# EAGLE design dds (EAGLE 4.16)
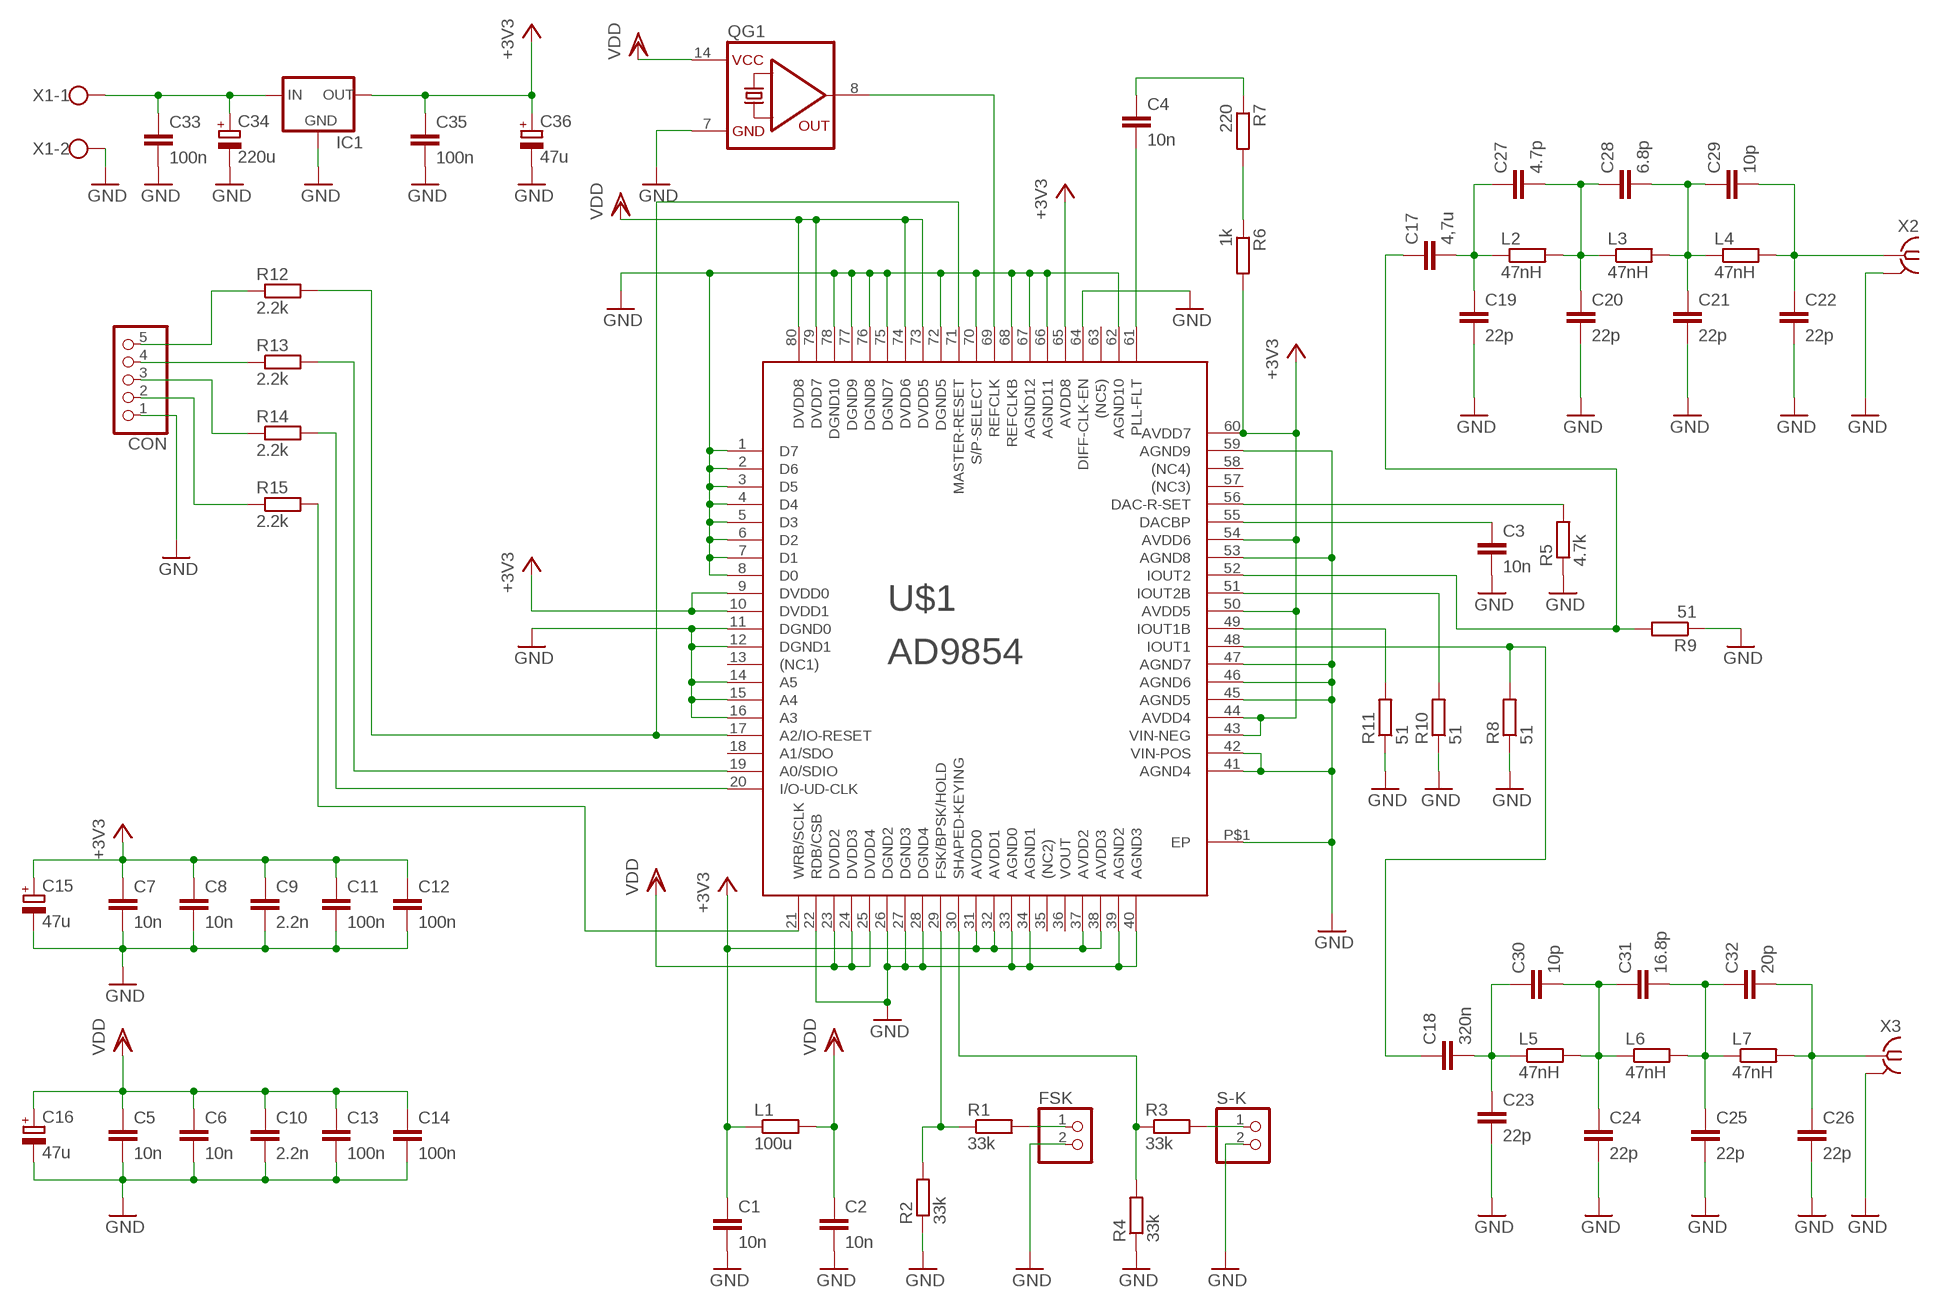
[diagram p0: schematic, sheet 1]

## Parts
C1  10n  C-EUC0805K  [C0805K]
C2  10n  C-EUC0805K  [C0805K]
C3  10n  C-EUC0805K  [C0805K]
C4  10n  C-EUC0805K  [C0805K]
C5  10n  C-EUC0805K  [C0805K]
C6  10n  C-EUC0805K  [C0805K]
C7  10n  C-EUC0805K  [C0805K]
C8  10n  C-EUC0805K  [C0805K]
C9  2.2n  C-EUC0603  [C0603]
C10  2.2n  C-EUC0603  [C0603]
C11  100n  C-EUC1206  [C1206]
C12  100n  C-EUC1206  [C1206]
C13  100n  C-EUC1206  [C1206]
C14  100n  C-EUC1206  [C1206]
C15  47u  CPOL-EUE2-4  [E2-4]
C16  47u  CPOL-EUE2-4  [E2-4]
C17  4,7u  C-EUC1206  [C1206]
C18  320n  C-EUC1206  [C1206]
C19  22p  C-EUC0805K  [C0805K]
C20  22p  C-EUC0805K  [C0805K]
C21  22p  C-EUC0805K  [C0805K]
C22  22p  C-EUC0805K  [C0805K]
C23  22p  C-EUC0805K  [C0805K]
C24  22p  C-EUC0805K  [C0805K]
C25  22p  C-EUC0805K  [C0805K]
C26  22p  C-EUC0805K  [C0805K]
C27  4.7p  C-EUC0805K  [C0805K]
C28  6.8p  C-EUC0805K  [C0805K]
C29  10p  C-EUC0805K  [C0805K]
C30  10p  C-EUC0805K  [C0805K]
C31  16.8p  C-EUC0805K  [C0805K]
C32  20p  C-EUC0805K  [C0805K]
C33  100n  C5/2.5  [C5B2.5]
C34  220u  CPOL-EUE2.5-6  [E2,5-6]
C35  100n  C5/2.5  [C5B2.5]
C36  47u  CPOL-EUE2-5  [E2-5]
CON  PINHD-1X5  [1X05]
FSK  PINHD-1X2  [1X02]
IC1  78XXS  [78XXS]
L1  100u  R-EU_0204/5  [0204/5]
L2  47nH  R-EU_M1206  [M1206]
L3  47nH  R-EU_M1206  [M1206]
L4  47nH  R-EU_M1206  [M1206]
L5  47nH  R-EU_M1206  [M1206]
L6  47nH  R-EU_M1206  [M1206]
L7  47nH  R-EU_M1206  [M1206]
QG1  QG5860  [DIL14S]
R1  33k  R-EU_M1206  [M1206]
R2  33k  R-EU_M1206  [M1206]
R3  33k  R-EU_M1206  [M1206]
R4  33k  R-EU_M1206  [M1206]
R5  4.7k  R-EU_R0805  [R0805]
R6  1k  R-EU_R0805  [R0805]
R7  220  R-EU_R0805  [R0805]
R8  51  R-EU_M1206  [M1206]
R9  51  R-EU_M1206  [M1206]
R10  51  R-EU_M1206  [M1206]
R11  51  R-EU_M1206  [M1206]
R12  2.2k  R-EU_0204/7  [0204/7]
R13  2.2k  R-EU_0204/7  [0204/7]
R14  2.2k  R-EU_0204/7  [0204/7]
R15  2.2k  R-EU_0204/7  [0204/7]
S-K  PINHD-1X2  [1X02]
U$1  AD9854  [TQFP80-917]
X1  W237-102  [W237-102]
X2  BU-SMA-H  [BU-SMA-H]
X3  BU-SMA-H  [BU-SMA-H]

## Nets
+3V3: C1.1 C7.1 C8.1 C9.1 C11.1 C12.1 C15.+ C35.1 C36.+ IC1.OUT L1.1 R6.2 U$1.9(DVDD0) U$1.10(DVDD1) U$1.31(AVDD0) U$1.32(AVDD1) U$1.37(AVDD2) U$1.38(AVDD3) U$1.43(VIN-NEG) U$1.44(AVDD4) U$1.50(AVDD5) U$1.54(AVDD6) U$1.60(AVDD7) U$1.65(AVDD8)
GND: C1.2 C2.2 C3.2 C5.2 C6.2 C7.2 C8.2 C9.2 C10.2 C11.2 C12.2 C13.2 C14.2 C15.- C16.- C19.2 C20.2 C21.2 C22.2 C23.2 C24.2 C25.2 C26.2 C33.2 C34.- C35.2 C36.- CON.1 FSK.2 IC1.GND QG1.7(GND) R2.1 R4.1 R5.1 R8.1 R9.1 R10.1 R11.1 S-K.2 U$1.1(D7) U$1.2(D6) U$1.3(D5) U$1.4(D4) U$1.5(D3) U$1.6(D2) U$1.7(D1) U$1.8(D0) U$1.11(DGND0) U$1.12(DGND1) U$1.14(A5) U$1.15(A4) U$1.16(A3) U$1.22(RDB/CSB) U$1.26(DGND2) U$1.27(DGND3) U$1.28(DGND4) U$1.33(AGND0) U$1.34(AGND1) U$1.39(AGND2) U$1.40(AGND3) U$1.41(AGND4) U$1.42(VIN-POS) U$1.45(AGND5) U$1.46(AGND6) U$1.47(AGND7) U$1.53(AGND8) U$1.59(AGND9) U$1.62(AGND10) U$1.64(DIFF-CLK-EN) U$1.66(AGND11) U$1.67(AGND12) U$1.68(REFCLKB) U$1.70(S/P-SELECT) U$1.72(DGND5) U$1.75(DGND7) U$1.76(DGND8) U$1.77(DGND9) U$1.78(DGND10) U$1.P$1(EP) X1.2 X2.2(GND) X3.2(GND)
N$1: R11.2 U$1.49(IOUT1B)
N$2: R1.1 R2.2 U$1.29(FSK/BPSK/HOLD)
N$3: FSK.1 R1.2
N$4: R3.1 R4.2 U$1.30(SHAPED-KEYING)
N$5: R3.2 S-K.1
N$6: C3.1 U$1.55(DACBP)
N$7: R5.2 U$1.56(DAC-R-SET)
N$8: C4.2 U$1.61(PLL-FLT)
N$9: C4.1 R7.1
N$10: R6.1 R7.2
N$11: QG1.8(OUT) U$1.69(REFCLK)
N$12: R10.2 U$1.51(IOUT2B)
N$13: C17.2 C19.1 C27.1 L2.1
N$14: C20.1 C27.2 C28.1 L2.2 L3.1
N$15: C21.1 C28.2 C29.1 L3.2 L4.1
N$16: C18.1 R8.2 U$1.48(IOUT1)
N$17: C17.1 R9.2 U$1.52(IOUT2)
N$18: C22.1 C29.2 L4.2 X2.1
N$19: C18.2 C23.1 C30.1 L5.1
N$20: C24.1 C30.2 C31.1 L5.2 L6.1
N$21: C25.1 C31.2 C32.1 L6.2 L7.1
N$22: C26.1 C32.2 L7.2 X3.1
N$23: R12.2 U$1.17(A2/IO-RESET) U$1.71(MASTER-RESET)
N$24: R13.2 U$1.19(A0/SDIO)
N$25: R14.2 U$1.20(I/O-UD-CLK)
N$26: R15.2 U$1.21(WRB/SCLK)
N$27: CON.5 R12.1
N$28: CON.4 R13.1
N$29: CON.3 R14.1
N$30: CON.2 R15.1
N$31: C33.1 C34.+ IC1.IN X1.1
VDD: C2.1 C5.1 C6.1 C10.1 C13.1 C14.1 C16.+ L1.2 QG1.14(VCC) U$1.23(DVDD2) U$1.24(DVDD3) U$1.25(DVDD4) U$1.73(DVDD5) U$1.74(DVDD6) U$1.79(DVDD7) U$1.80(DVDD8)
Unconnected: U$1.13((NC1)) U$1.18(A1/SDO) U$1.35((NC2)) U$1.36(VOUT) U$1.57((NC3)) U$1.58((NC4)) U$1.63((NC5))

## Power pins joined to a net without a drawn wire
GND: X2.3(GND) X2.4(GND) X2.5(GND) X3.3(GND) X3.4(GND) X3.5(GND)

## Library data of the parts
C1-C14 C17-C32 = rcl:C-EU: CAPACITOR, European symbol
C15 C16 C34 C36 = rcl:CPOL-EU: POLARIZED CAPACITOR, European symbol
C33 C35 = capacitor-wima:C: CAPACITOR
CON = pinhead:PINHD-1X5: PIN HEADER
FSK S-K = pinhead:PINHD-1X2: PIN HEADER
IC1 = v-reg:78XXS: VOLTAGE REGULATOR
L1-L7 R1-R15 = rcl:R-EU_: RESISTOR, European symbol
QG1 = crystal:QG5860: CRYSTAL RESONATOR
U$1 = analog-devices-dds:AD9854
X1 = con-wago-500:W237-102: WAGO SCREW CLAMP
X2 X3 = con-coax:BU-SMA-H: FEMALE SMA CONNECTOR Radiall distributor RS 193-9325

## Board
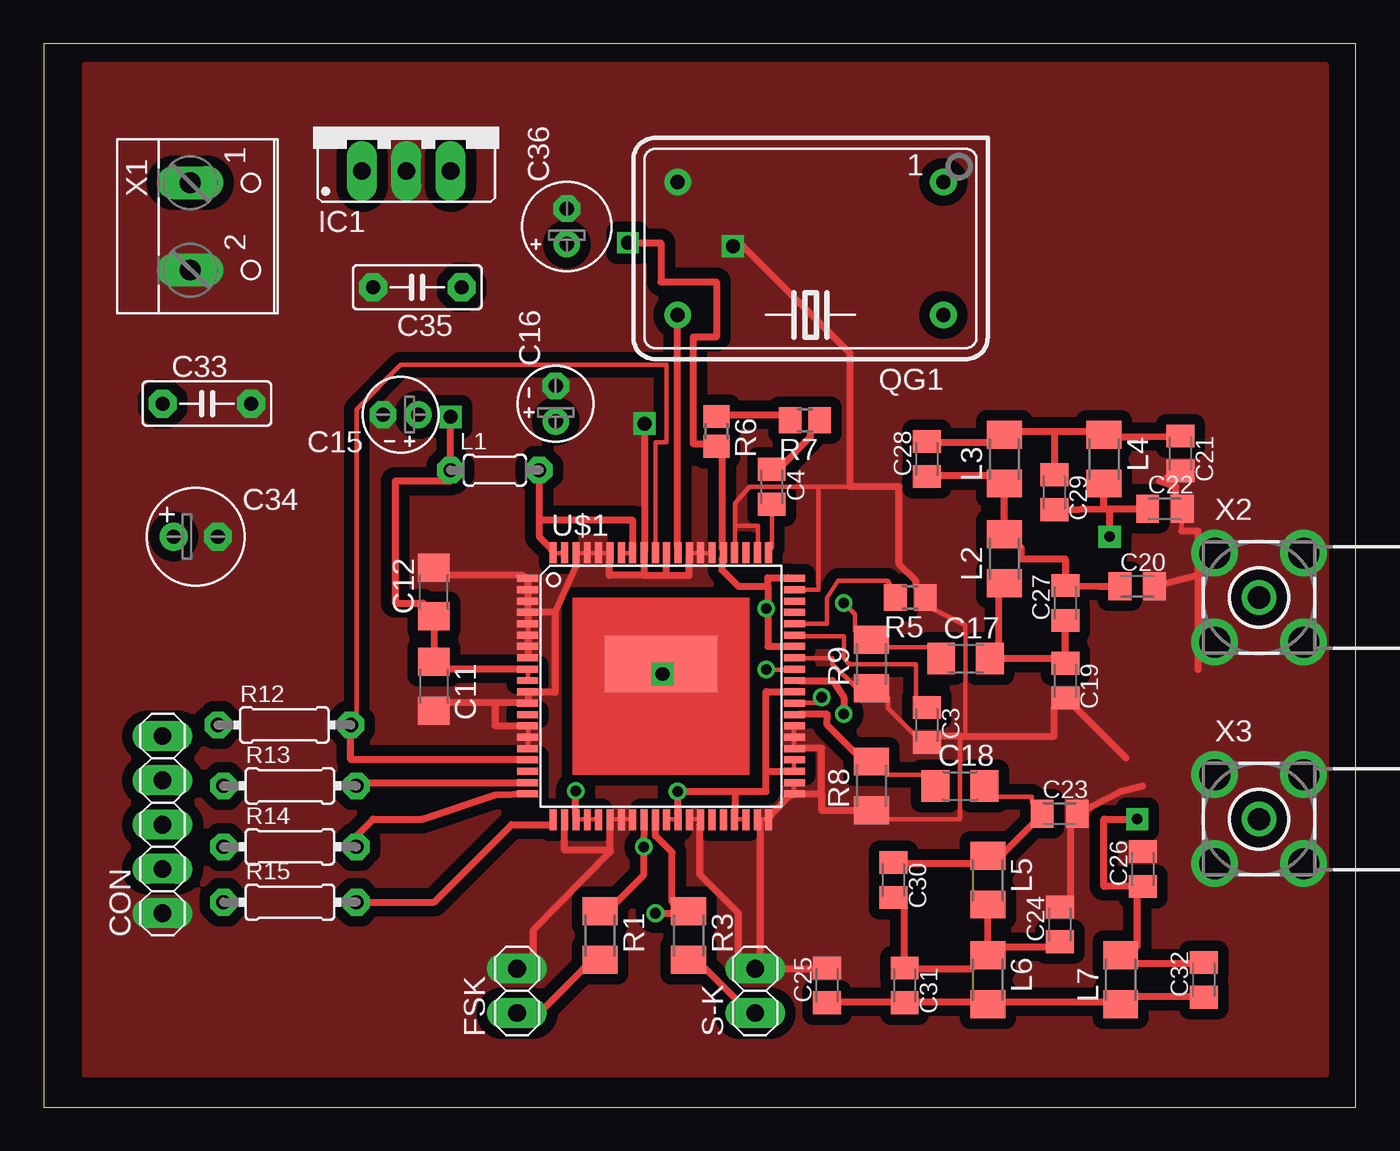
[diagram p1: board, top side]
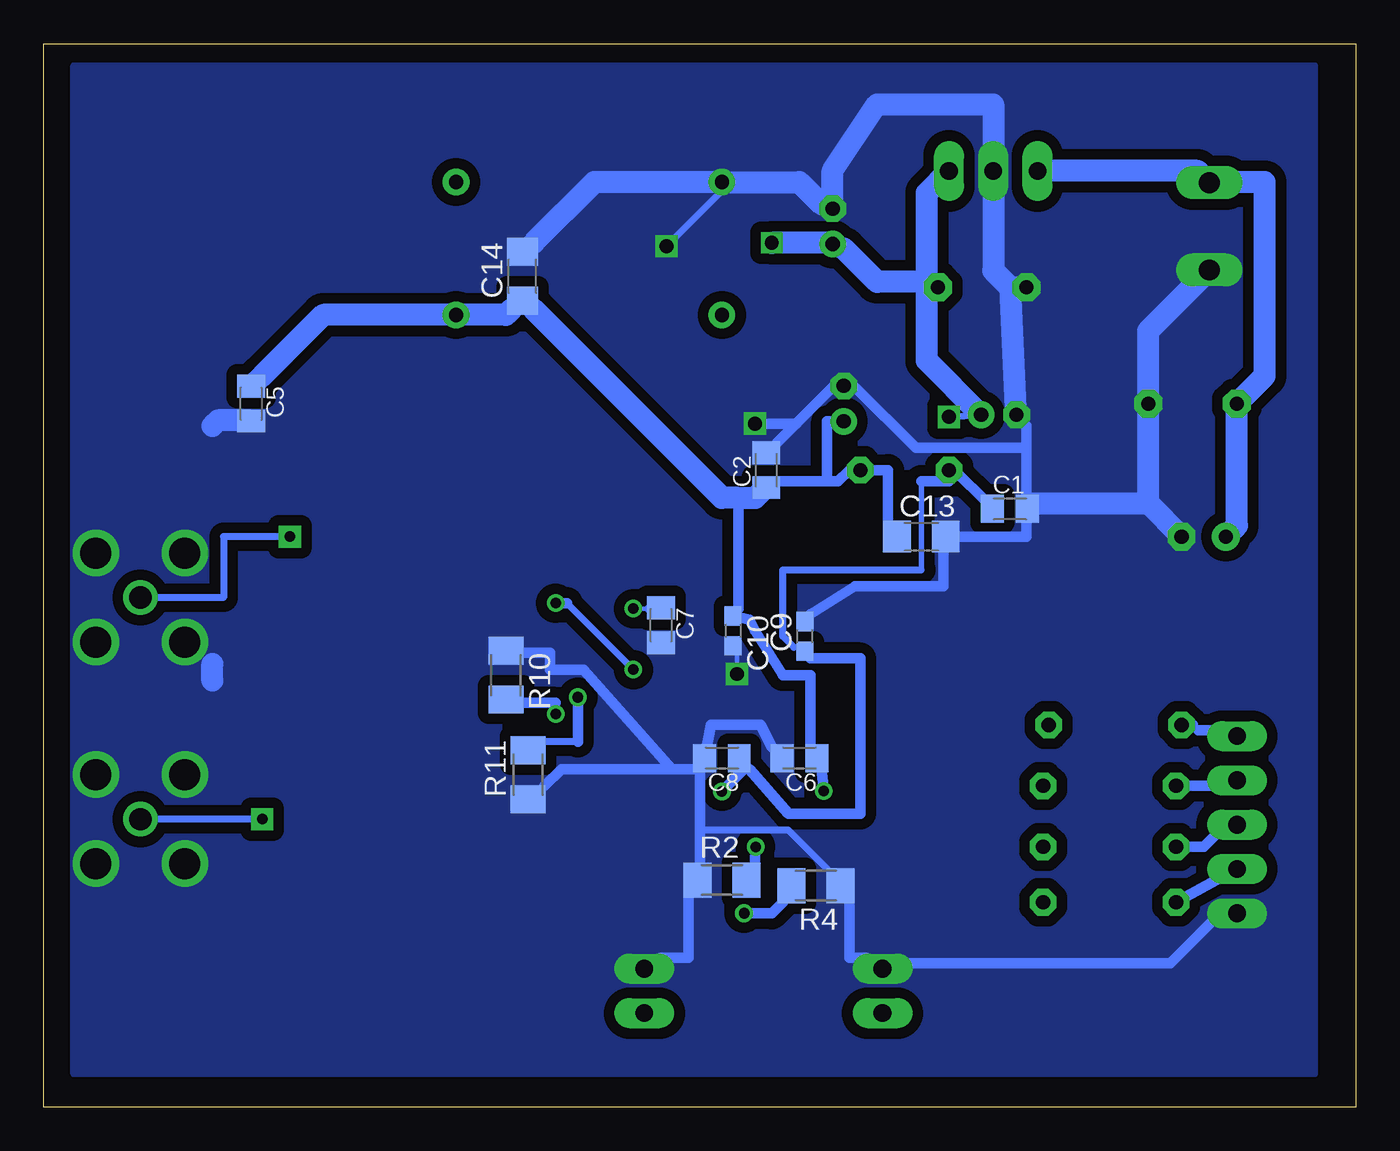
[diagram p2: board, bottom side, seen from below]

Size 75.23 x 60.95 mm. Coordinates in mm from the lower left corner, seen from the top.
Outline: 0,0 75.23,0 75.23,60.95 0,60.95 0,0
Copper layers (1*16): Top 0.035mm / dielectric 1.5mm / Bottom 0.035mm
Design rules "default": minimum track width 10mil, minimum drill 24mil, track to track 8mil, track to pad 8mil, pad to pad 8mil, via to via 8mil, smd to smd 8mil, copper to edge 40mil, drill to drill 8mil, minimum pad ring 14mil, minimum via ring 8mil, stop-mask expansion 4mil, vias tented up to drill 0mil, thermal gap 10mil

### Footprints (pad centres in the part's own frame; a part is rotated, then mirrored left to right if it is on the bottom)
C0805K = smd 1.3 x 1.6: 1 -1,0; 2 1,0
C0603 = smd 1.1 x 1: 1 -0.85,0; 2 0.85,0
C1206 = smd 1.6 x 1.8: 1 -1.4,0; 2 1.4,0
E2-4 = drill 0.813 pad 1.27 round: + -1.016,0 | drill 0.813 pad 1.27 octagon: - 1.016,0
C5B2.5 = drill 0.813 pad 1.6 octagon: 1 -2.54,0; 2 2.54,0
E2,5-6 = drill 0.813 pad 1.6 round: + -1.27,0 | drill 0.813 pad 1.6 octagon: - 1.27,0
E2-5 = drill 0.813 pad 1.27 round: + -1.016,0 | drill 0.813 pad 1.27 octagon: - 1.016,0
1X05 = drill 1.016 long: 1 -5.08,0; 2 -2.54,0; 3 0,0; 4 2.54,0; 5 5.08,0
1X02 = drill 1.016 long: 1 -1.27,0; 2 1.27,0
78XXS = drill 1.016 long: GND 0,-2.54; IN -2.54,-2.54; OUT 2.54,-2.54
0204/5 = drill 0.813 octagon: 1 -2.54,0; 2 2.54,0
M1206 = smd 1.6 x 2: 1 -1.4,0; 2 1.4,0
DIL14S = drill 0.813 round: 1 -7.62,-3.81; 7 7.62,-3.81; 8 7.62,3.81; 14 -7.62,3.81
R0805 = smd 1.3 x 1.5: 1 -0.85,0; 2 0.85,0
0204/7 = drill 0.813 octagon: 1 -3.81,0; 2 3.81,0
TQFP80-917 = smd 1.2 x 0.4: 1 -7.65,4.905; 2 -7.65,4.255; 3 -7.65,3.605; 4 -7.65,2.955; 5 -7.65,2.305; 6 -7.65,1.655; 7 -7.65,1.005; 8 -7.65,0.355; 9 -7.65,-0.295; 10 -7.65,-0.945; 11 -7.65,-1.595; 12 -7.65,-2.245; 13 -7.65,-2.895; 14 -7.65,-3.545; 15 -7.65,-4.195; 16 -7.65,-4.845; 17 -7.65,-5.495; 18 -7.65,-6.145; 19 -7.65,-6.795; 20 -7.65,-7.445; 41 7.65,-7.445; 42 7.65,-6.795; 43 7.65,-6.145; 44 7.65,-5.495; 45 7.65,-4.845; 46 7.65,-4.195; 47 7.65,-3.545; 48 7.65,-2.895; 49 7.65,-2.245; 50 7.65,-1.595; 51 7.65,-0.945; 52 7.65,-0.295; 53 7.65,0.355; 54 7.65,1.005; 55 7.65,1.655; 56 7.65,2.305; 57 7.65,2.955; 58 7.65,3.605; 59 7.65,4.255; 60 7.65,4.905 | smd 0.4 x 1.2: 21 -6.175,-8.92; 22 -5.525,-8.92; 23 -4.875,-8.92; 24 -4.225,-8.92; 25 -3.575,-8.92; 26 -2.925,-8.92; 27 -2.275,-8.92; 28 -1.625,-8.92; 29 -0.975,-8.92; 30 -0.325,-8.92; 31 0.325,-8.92; 32 0.975,-8.92; 33 1.625,-8.92; 34 2.275,-8.92; 35 2.925,-8.92; 36 3.575,-8.92; 37 4.225,-8.92; 38 4.875,-8.92; 39 5.525,-8.92; 40 6.175,-8.92; 61 6.175,6.38; 62 5.525,6.38; 63 4.875,6.38; 64 4.225,6.38; 65 3.575,6.38; 66 2.925,6.38; 67 2.275,6.38; 68 1.625,6.38; 69 0.975,6.38; 70 0.325,6.38; 71 -0.325,6.38; 72 -0.975,6.38; 73 -1.625,6.38; 74 -2.275,6.38; 75 -2.925,6.38; 76 -3.575,6.38; 77 -4.225,6.38; 78 -4.875,6.38; 79 -5.525,6.38; 80 -6.175,6.38 | smd 6.452 x 3.251: P$1 0,0
W237-102 = drill 1.194 long: 1 -2.5,-1.27; 2 2.5,-1.27
BU-SMA-H = drill 1.27 round: 1 0,0 | drill 1.778 round: 2 -2.55,2.55; 3 2.55,2.55; 4 2.55,-2.55; 5 -2.55,-2.55

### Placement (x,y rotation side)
C1  19.84,34.29 0 bottom
C2  33.81,36.51 90 bottom
C3  50.64,21.9 270 top
C4  41.74,35.55 270 top
C5  63.33,40.32 270 bottom
C6  31.9,20 180 bottom
C7  39.84,27.62 270 bottom
C8  36.35,20 180 bottom
C9  31.59,26.98 90 bottom
C10  35.71,27.3 270 bottom
C11  22.38,24.12 270 top
C12  22.38,29.52 90 top
C13  24.92,32.7 0 bottom
C14  47.78,47.62 90 bottom
C15  20.47,39.68 180 top
C16  29.36,40.32 90 top
C17  52.86,25.71 0 top
C18  52.54,18.41 0 top
C19  58.57,24.44 270 top
C20  62.7,29.84 0 top
C21  65.18,37.46 270 top
C22  64.29,34.29 0 top
C23  58.25,16.82 0 top
C24  58.25,10.47 90 top
C25  44.92,6.98 90 top
C26  63.02,13.65 90 top
C27  58.57,28.89 90 top
C28  50.64,37.14 90 top
C29  57.94,35.24 270 top
C30  48.73,13.01 270 top
C31  49.36,6.98 270 top
C32  66.51,7.3 90 top
C33  9.36,40.32 0 top
C34  8.72,32.7 0 top
C35  21.42,46.98 180 top
C36  30,50.48 90 top
CON  6.82,16.19 90 top
FSK  27.14,6.66 90 top
IC1  20.79,56.19 0 top
L1  25.87,36.51 0 top
L2  55.08,31.43 90 top
L3  55.08,37.14 90 top
L4  60.8,37.14 270 top
L5  54.13,13.01 270 top
L6  54.13,7.3 270 top
L7  61.75,7.3 90 top
QG1  43.97,49.21 180 top
R1  31.9,9.84 270 top
R2  36.35,13.01 0 bottom
R3  36.98,9.84 270 top
R4  30.95,12.7 180 bottom
R5  49.68,29.21 180 top
R6  38.57,38.73 270 top
R7  43.65,39.37 180 top
R8  47.46,18.41 90 top
R9  47.46,25.4 90 top
R10  48.73,24.76 270 bottom
R11  47.46,19.05 90 bottom
R12  13.81,21.9 0 top
R13  14.12,18.41 0 top
R14  14.12,14.92 0 top
R15  14.12,11.74 0 top
S-K  40.79,6.66 90 top
U$1  35.39,25.4 0 top
X1  9.68,50.48 270 top
X2  69.69,29.21 0 top
X3  69.69,16.51 0 top

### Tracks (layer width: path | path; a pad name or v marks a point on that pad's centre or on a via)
+3V3  (via drill 0.61, 0.8, 0.8 pad 1.27)
  Top 0.254: U$1.31 35.71,16.51 36.35,16.51 U$1.32 36.35,16.82 | U$1.38 40.16,16.51 39.65,16.51 U$1.37 39.65,16.85 | U$1.43 43.02,19.36 43.02,20 U$1.44 | U$1.10 27.77,24.44 27.77,25.08 U$1.9 27.33,25.11 | C11.1 22.89,25.11 | R6.2 38.89,37.46 | 42.7,26.41 U$1.54 | 42.7,30.35 U$1.60 | 41.52,28.89 v41.43,28.57
  Top 0.406: 36.35,16.82 v36.35,18.09 39.65,18.09 | 39.65,18.09 39.65,16.85 | 41.43,19.23 41.43,23.81 42.7,23.81 U$1.50 | 41.43,19.23 42.7,19.23 U$1.43 | 22.89,25.11 27.33,25.11 | C11.1 C12.1 21.74,28.89 20.16,28.89 20.16,35.87 23.33,35.87 L1.1 v23.33,39.55 | 38.89,37.46 38.89,32.06 U$1.65 38.89,31.43 38.89,30.79 39.84,29.84 41.52,29.84 | 42.7,26.41 41.52,26.41 41.52,28.89 41.52,29.84 | 41.52,29.84 41.52,30.35 42.7,30.35 | 39.65,18.09 41.43,18.09 41.43,19.23 | R6.2 37.94,38.03 37.24,38.03 37.24,44.13 38.57,44.13 38.57,47.3 35.39,47.3 35.39,49.52 v33.49,49.52
  Bottom 0.254: 31.27,25.71 C9.1 31.9,26.35 32.22,26.35 | 34.76,19.36 C8.1 35.08,19.36 | C7.1 40.48,28.89 | 24.47,47.24 24.6,47.3 | 29.68,49.52 29.93,49.52 C36.+ | v41.43,28.57 40.48,28.57
  Bottom 0.305: 24.92,30.79 24.92,35.87
  Bottom 0.406: 32.22,26.35 32.85,26.98 32.85,30.79 24.92,30.79 | v23.33,39.55 C15.+
  Bottom 0.61: 31.27,25.71 28.41,25.71 28.41,16.82 32.54,16.82 34.76,19.36 | 24.92,35.87 23.33,35.87 L1.1 23.01,36.19 22.7,36.19 21.42,34.92 C1.1 | 35.08,19.36 v36.35,18.09 | 24.6,47.11 24.47,47.24 | 40.48,28.57 C7.1
  Bottom 1.27: C36.+ 29.36,49.21 27.46,47.3 24.6,47.3 24.6,52.38 IC1.OUT | 24.47,47.24 C35.1 | 29.93,49.52 v33.49,49.52 | C15.+ 24.6,42.79 24.6,47.11
GND  (via drill 0.8 pad 1.27)
  Top 0.254: 27.77,21.27 27.77,20.63 U$1.16 | 27.77,21.27 27.77,21.9 U$1.14 27.46,21.87 | 27.77,21.27 U$1.15 | 27.77,23.17 U$1.12 27.46,23.17 | U$1.11 27.77,23.81 | 23.01,23.17 C11.2 | 37.62,31.75 36.98,31.75 U$1.68 | 37.62,31.75 38.25,31.75 U$1.66 | 37.62,31.75 U$1.67 | 31.27,31.75 30.63,31.75 | 31.9,31.75 31.27,31.75 | 31.27,31.75 U$1.77 | 31.9,31.75 32.54,31.75 U$1.75 | 31.9,31.75 U$1.76 | 27.77,30.16 U$1.1 | 27.77,25.9 U$1.8 | 27.77,26.98 27.77,27.62 U$1.5 | 27.77,26.35 U$1.7 | U$1.4 27.77,28.25 | 27.77,28.89 U$1.3 | 32.54,16.51 33.17,16.51 | 33.17,16.51 33.81,16.51 U$1.28 | 33.17,16.51 U$1.27 | 32.47,14.63 32.47,14.73 | 43.02,21.27 43.02,20.63 U$1.45 | 43.02,21.27 43.02,21.9 U$1.47 | 43.02,21.27 U$1.46 | U$1.40 41.43,16.51 41.11,16.51 U$1.39 41.11,16.19 | U$1.41 43.02,18.09 43.02,18.41 U$1.42 | U$1.33 36.98,16.51 37.62,16.51 U$1.34 37.62,16.19 | 44.28,7.93 C25.2 | 64.92,34.29 C22.2 65.24,33.02 | 39.65,33.33 39.64,34.6 40.48,35.55 44.41,35.55 | 39.65,33.33 39.65,32.06 U$1.64 | 46.25,35.55 44.41,35.55 | U$1.53 43.33,25.71 45.24,25.71 45.24,25.4 46.51,24.12 R9.1 48.41,23.49 48.41,22.86 50,21.27 C3.2 | C24.2 58.89,12.06 | 58.89,16.19 C23.2 | C19.2 59.21,22.86 | 52.86,21.27 52.86,27.62 50.95,28.57 R5.1 | 52.54,21.27 52.54,16.51 48.41,16.51 R8.1 | U$1.62 40.95,31.78 40.95,33.33 39.65,33.33 | U$1.59 44.41,29.65 44.41,35.55 | 35.39,25.3 U$1.P$1 35.39,25.78 v35.49,24.82 | U$1.22
  Top 0.406: 27.77,23.81 27.77,23.17 | 25.87,23.17 23.01,23.17 | 27.46,23.17 25.87,23.17 | 27.46,21.87 25.87,21.87 25.87,23.17 | 34.41,30.48 34.41,31.43 U$1.72 34.44,31.78 v34.44,39.17 | 34.41,30.48 35.71,30.48 | 35.71,30.48 35.71,31.43 U$1.70 | 35.71,30.48 37.01,30.48 37.01,31.43 U$1.68 | 30.63,31.75 U$1.78 30.54,31.36 30.5,30.98 29.33,28.35 | 27.77,30.16 27.77,29.84 U$1.2 27.77,29.52 27.77,28.89 27.77,28.25 27.77,27.62 | 27.77,25.9 27.77,26.35 27.77,26.98 U$1.6 | C12.2 23.01,30.48 27.46,30.48 U$1.1 | 29.33,28.35 28.12,28.35 U$1.4 | 34.41,30.48 32.44,30.48 32.44,31.4 U$1.75 | 29.33,28.35 29.33,23.78 28.06,23.78 U$1.11 | 32.54,16.51 U$1.26 32.47,16.19 32.47,14.73 29.87,14.73 U$1.22 | 32.47,14.63 28.09,10.15 28.09,8.57 FSK.2 | U$1.40 41.74,16.82 42.7,17.78 U$1.41 44.6,17.97 | 44.6,17.97 44.6,20.57 43.33,20.57 U$1.45 | 44.6,17.97 44.6,17.01 R8.1 | 37.62,16.19 37.62,13.33 39.84,11.11 39.84,8.57 S-K.2 | S-K.2 44.28,7.93 | 41.11,16.19 41.11,8.57 S-K.2 | 64.92,34.29 64.92,35.55 63.97,35.87 C21.2 | 65.24,33.02 66.19,33.02 66.19,30.48 | 66.19,25.08 66.19,30.48 | R5.1 50,29.84 50,30.16 49.05,31.11 49.05,35.55 46.25,35.55 46.25,43.18 40.09,49.33 v39.52,49.33 | 58.89,12.06 58.89,16.19 | 63.02,18.41 61.75,18.09 C23.2 | 59.21,22.86 62.06,20 | C3.2 51.27,21.27 52.54,21.27 52.86,21.27 57.94,21.27 57.94,22.86 C19.2 | 66.19,30.48 C20.2
  Bottom 0.254: 31.27,28.25 C9.2 | 47.14,49.52 C14.2 | 33.17,38.1 C2.2 | 29.05,11.74 R4.1 30.31,13.65 | 46.51,18.41 R11.1 | 37.94,19.36 C8.2 37.62,19.36 | 38.25,12.06 R2.1 37.62,13.97 | 65.56,24.44 65.24,25.71 | C10.2 35.49,26.45 v35.49,24.82 | 32.06,39.21 | 32.06,39.21 32.06,39.17 | 18.88,34.29 C1.2
  Bottom 0.406: 30.31,13.65 32.54,15.87 37.62,15.87 | QG1.7 36.35,52.51 v39.52,49.33
  Bottom 0.61: 31.27,28.25 28.73,29.84 23.65,29.84 23.65,32.06 C13.2 18.88,32.7 18.88,34.29 18.88,37.78 | 18.88,37.78 18.88,39.05 C15.- 19.52,40.06 | 33.17,38.1 32.06,39.21 30,41.27 C16.- 28.73,41.27 25.23,37.78 18.88,37.78 | 29.05,11.74 29.05,8.57 28.09,8.57 FSK.2 25.87,8.25 10.63,8.25 8.09,10.79 CON.1 | C6.2 33.49,20.63 34.12,21.9 36.98,21.9 C8.2 | 46.51,18.41 45.55,19.36 39.2,19.36 | 37.94,19.36 39.2,19.36 | 39.2,19.36 44.28,25.08 46.19,25.08 46.19,26.03 48.6,26.03 R10.1 | 38.25,12.06 38.25,8.57 39.84,8.57 S-K.2 | 37.62,13.97 37.62,15.87 37.62,19.36 | 32.06,39.17 v34.44,39.17 | C1.2 18.52,34.6
  Bottom 1.27: 47.14,49.52 43.65,53.02 QG1.7 31.9,53.02 30.63,51.75 C36.- | X1.2 11.9,44.48 C33.2 11.9,34.6 | 11.9,34.6 C34.- | 18.52,34.6 11.9,34.6 | 19.84,46.98 20.79,47.94 IC1.GND 20.79,57.46 27.46,57.46 30,53.65 C36.- | 19.84,46.98 C35.2 | C36.- 30,51.43 | 19.84,46.98 19.52,40.06 | 65.56,24.44 65.56,25.4 | C5.2 63.33,39.37 65.24,39.37 65.56,39.05
  pour Top (isolate 0.61, no thermals): 2.38,59.69 2.38,1.9 73.5,1.9 73.5,59.69
  pour Bottom (isolate 0.61, no thermals): 2.38,59.69 2.38,1.9 73.5,1.9 73.5,59.69
N$1  (via drill 0.61)
  Top 0.254: v44.6,23.49 44.6,23.17 43.33,23.17 U$1.49
  Bottom 0.254: 46.51,20.95 R11.2
  Bottom 0.406: 44.6,20.95 46.51,20.95
  Bottom 0.61: 44.6,20.95 v44.6,23.49
N$2  (via drill 0.61)
  Top 0.254: R1.1 32.85,11.74
  Top 0.406: 32.85,11.74 34.41,13.33 v34.41,14.92 34.44,16.19 U$1.29
  Bottom 0.254: 34.44,13.97 R2.2
  Bottom 0.61: v34.41,14.92 34.44,13.97
N$3
  Top 0.406: R1.2 30.95,7.93 28.41,5.39 FSK.1
N$4  (via drill 0.61)
  Top 0.254: 35.08,16.19 U$1.30 | 36.03,11.74 R3.1 36.03,11.11
  Top 0.406: 35.08,16.19 35.08,15.55 36.03,14.6 36.03,11.74 | v35.08,11.11 36.03,11.11
  Bottom 0.254: R4.2 32.85,11.74
  Bottom 0.61: 32.85,11.74 33.49,11.11 v35.08,11.11
N$5
  Top 0.406: R3.2 37.94,7.93 39.84,6.03 S-K.1
N$6
  Top 0.254: U$1.55 43.33,26.98 45.87,26.98 45.87,25.71 46.19,25.4 50,25.4 50,23.49 C3.1
N$7
  Top 0.254: U$1.56 43.33,27.71 44.92,27.71 44.92,29.21 45.55,30.16 48.41,30.16 R5.2
N$8
  Top 0.254: U$1.61 41.74,32.06 C4.2
N$9
  Top 0.254: C4.1 42.38,36.83
  Top 0.406: 42.38,36.83 43.97,38.41 43.97,38.73 R7.1
N$10
  Top 0.254: 42.38,39.68 R7.2
  Top 0.406: 42.38,39.68 39.2,39.68 R6.1
N$11
  Top 0.254: U$1.69 36.35,32.06
  Top 0.406: 36.35,32.06 QG1.8
N$12  (via drill 0.61)
  Top 0.254: U$1.51 43.33,24.44
  Top 0.406: 43.33,24.44 45.24,24.44 45.36,24.27 45.87,23.49 v45.87,22.54
  Bottom 0.254: v45.87,22.54 45.87,23.17
  Bottom 0.61: R10.2 48.54,23.17 45.87,23.17
N$13
  Top 0.254: 57.94,25.71 C19.1 | 54.76,29.52 L2.1 | C17.2 54.76,26.35
  Top 0.406: C19.1 C27.1 | C17.2 57.94,25.71 | 54.76,26.35 54.76,29.52
N$14
  Top 0.254: 50.95,36.19 C28.1 | L3.1 54.13,36.19
  Top 0.406: 54.13,36.19 50.95,36.19 | L3.1 L2.2 56.03,32.06 56.03,31.43 58.57,31.43 C27.2 60.48,29.84 C20.1
N$15
  Top 0.254: C28.2 50.95,38.1 | 54.13,38.1 L3.2 56.03,38.73
  Top 0.406: 50.95,38.1 54.13,38.1 | C21.1 62.7,38.41 61.75,38.41 L4.1 59.84,38.73 57.94,38.73 | 56.03,38.73 57.94,38.73 | 57.94,38.73 C29.1
N$16
  Top 0.254: 46.51,20.32 R8.2 48.41,19.05 50.64,19.05 C18.1
  Top 0.406: 46.51,20.32 44.92,21.9 44.94,22.51 43.35,22.51 U$1.48
N$17  (via drill 0.61)
  Top 0.254: v41.43,25.08 42.7,25.08 U$1.52 | v45.87,28.89 46.51,28.25 46.51,27.3 R9.2 48.41,26.35 50.95,26.35 C17.1
  Bottom 0.406: v41.43,25.08 45.24,28.89
  Bottom 0.61: 45.24,28.89 v45.87,28.89
N$18  (via drill 0.6 pad 1.27)
  Top 0.406: C22.1 62.38,34.29 61.11,34.28 | 60.79,34.28 61.11,34.28 | C29.2 60.79,34.28 | 60.79,34.28 60.78,34.31 L4.2 | 61.11,34.28 61.11,34.29 | 61.11,34.28 v61.11,32.7
  Bottom 0.406: X2.1 64.92,29.21 64.92,32.7 v61.11,32.7
N$19
  Top 0.254: C30.1 49.36,13.97 | 53.17,13.97 L5.1 | C18.2 54.44,17.78 56.67,17.78 56.67,17.46 C23.1
  Top 0.406: 49.36,13.97 53.17,13.97 | C23.1 56.67,16.19 55.08,14.6 L5.1
N$20
  Top 0.254: 57.62,9.2 C24.1
  Top 0.406: C30.2 49.36,11.43 C31.1 50,7.93 53.17,7.93 L6.1 | 57.62,9.2 55.08,9.2 L6.1 | L6.1 L5.2
N$21
  Top 0.254: 65.88,6.35 C32.1 | L7.1 62.7,6.35 | 53.17,6.03 L6.2
  Top 0.406: 62.7,6.35 65.88,6.35 | C25.1 45.55,6.03 48.73,6.03 C31.2 50,6.03 53.17,6.03 | L7.1 60.8,6.03 55.08,6.03 L6.2
N$22  (via drill 0.6 pad 1.27)
  Top 0.254: 62.7,12.06 C26.1 | L7.2 62.7,9.2 | 65.88,8.25 C32.2
  Top 0.406: 62.7,9.2 62.7,12.06 | 65.88,8.25 62.7,8.25 L7.2 | C26.1 60.8,12.65 60.8,16.51 v62.7,16.51
  Bottom 0.406: v62.7,16.51 X3.1
N$23
  Top 0.254: 27.46,19.93 U$1.17 | U$1.71 35.08,32.06 35.08,38.1 35.71,38.1 35.71,42.54 20.47,42.54 17.93,40 17.93,22.54 R12.2
  Top 0.406: 27.46,19.93 17.62,19.93 R12.2
N$24
  Top 0.406: R13.2 17.84,18.41 17.84,18.6 U$1.19
N$25
  Top 0.406: U$1.20 25.87,17.9 21.71,16.51 18.88,16.51 17.93,15.55 R14.2
N$26
  Top 0.254: 29.05,16.19 U$1.21
  Top 0.406: 29.05,16.19 26.82,16.19 22.38,11.74 R15.2
N$27
  Bottom 0.254: 9.04,21.59 9.36,21.9
  Bottom 0.61: 9.04,21.59 8.09,21.59 CON.5 | 9.36,21.9 R12.1
N$28
  Bottom 0.61: CON.4 7.14,18.41 R13.1
N$29
  Bottom 0.61: CON.3 7.77,15.87 8.72,14.92 R14.1
N$30
  Bottom 0.61: CON.2 R15.1
N$31
  Bottom 0.61: 8.41,53.02 X1.1
  Bottom 1.27: C34.+ 6.82,33.33 C33.1 5.23,41.91 5.23,53.02 8.41,53.02 | X1.1 9.08,53.65 IC1.IN
VDD  (via drill 0.61)
  Top 0.254: U$1.80 29.36,31.75 29.68,31.75 U$1.79 | U$1.74 33.17,31.75 33.81,31.75 U$1.73 | 31.27,16.51 30.63,16.51 U$1.23 | 31.27,16.51 31.81,16.51 U$1.25 | 31.27,16.51 U$1.24
  Top 0.406: U$1.80 29.05,32.06 28.41,32.7 28.41,33.65 | L1.2 28.41,33.65 | v30.5,18.12 30.5,16.85 U$1.23 | U$1.73 33.76,33.65 28.41,33.65
  Bottom 0.254: 48.41,45.72 C14.1 47.14,45.72 | 30.63,19.36 C6.1 | C2.1 33.17,35.87
  Bottom 0.61: C13.1 26.82,33.33 26.82,36.51 L1.2 29.05,36.51 29.68,35.87 30.31,35.87 | 35.39,34.92 35.39,28.57 C10.1 34.76,27.94 34.44,27.3 32.85,24.76 31.27,24.76 31.27,20.63 C6.1 | v30.5,18.12 30.63,19.36 | 33.17,35.87 30.31,35.87 | C16.+ 30.31,39.3 30.31,35.87
  Bottom 1.27: C5.1 62.7,41.91 59.21,45.4 QG1.14 48.73,45.4 48.41,45.72 | C2.1 34.44,34.92 35.39,34.92 36.35,34.92 47.14,45.72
